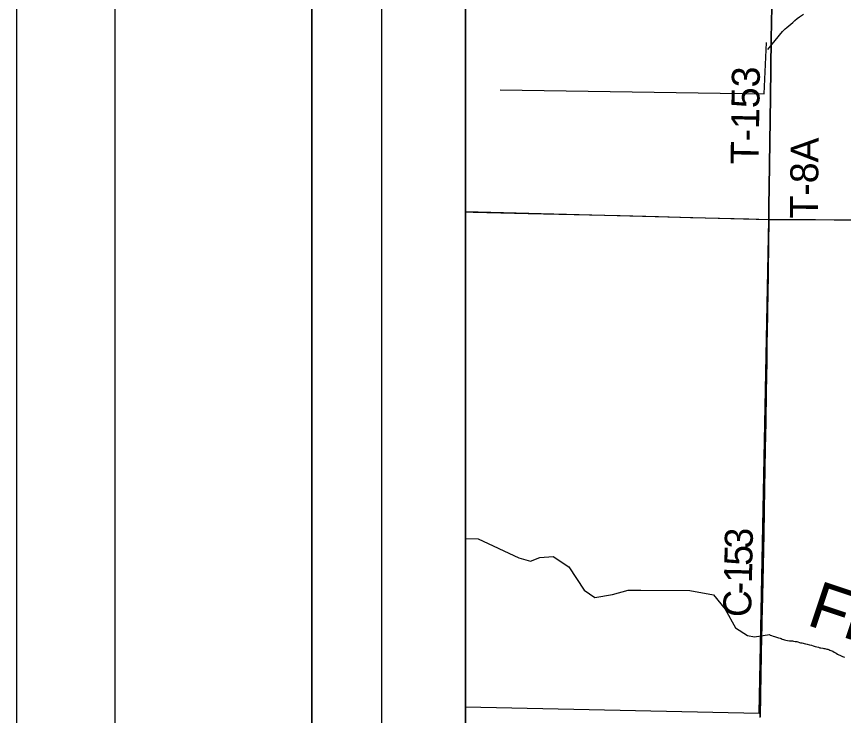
# Model space of a CAD drawing. Extents: x -483 to 680, y 0 to 440.
# Drawn here: x 0 to 84, y 177.8 to 248.8 of the extents above; entities that cross this region are included whole.
import ezdxf

# ---------------------------------------------------------------- set-up
doc = ezdxf.new("R2010")
doc.units = 0
for name, color, linetype in [('GM_X_County_Road', 7, 'Continuous'), ('GM_X_County_Road_Text', 7, 'Continuous'), ('GM_X_Minor_River', 7, 'Continuous'), ('GM_X_Minor_River_Text', 7, 'Continuous'), ('GM_X_State_Shield', 7, 'Continuous'), ('GM_X_Township_Road', 7, 'Continuous'), ('GM_X_Township_Road_Text', 7, 'Continuous'), ('SH_Border', 7, 'Continuous'), ('SH_Cut_Line', 7, 'Continuous'), ('SH_Text', 7, 'Continuous')]:
    doc.layers.add(name, color=color, linetype=linetype)

msp = doc.modelspace()

# ---------------------------------------------------------------- linework, layer by layer
at = {"layer": 'GM_X_County_Road'}
for points in [[(45.608, 228.974), (46.378, 228.954), (51.973, 228.809), (61.298, 228.597), (65.182, 228.502), (68.446, 228.413), (74.35, 228.254), (76.405, 228.209)], [(75.661, 185.894), (75.682, 186.78), (75.698, 187.554), (75.717, 188.462), (75.831, 192.963), (75.893, 196.227), (75.982, 200.889), (76.047, 204.929), (76.093, 207.57), (76.133, 210.679), (76.19, 213.71), (76.218, 215.223), (76.252, 217.206), (76.265, 218.163), (76.282, 219.286), (76.296, 220.314), (76.405, 228.209)], [(76.405, 228.209), (77.732, 228.207), (79.536, 228.205), (81.122, 228.199), (83.017, 228.168), (84.29, 228.169), (85.658, 228.165), (90.256, 228.152), (92.929, 228.14), (100.852, 228.125), (108.125, 228.103), (111.636, 228.062), (116.763, 227.999), (126.559, 227.882)], [(75.532, 177.624), (75.533, 177.672), (75.602, 182.027), (75.661, 185.894)]]:
    msp.add_lwpolyline(points, dxfattribs=at)
at = {"layer": 'GM_X_Minor_River'}
for points in [[(76.295, 245.472), (77.777, 247.291), (77.915, 247.419), (78.052, 247.548), (78.228, 247.694), (78.424, 247.859), (78.62, 248.043), (78.835, 248.207), (79.05, 248.39), (79.267, 248.611), (79.52, 248.774), (79.91, 249.065)], [(49.107, 241.377), (75.936, 240.958), (76.173, 246.166)], [(45.608, 195.807), (46.881, 195.778), (51.004, 193.866), (52.182, 193.52), (53.152, 193.898), (54.483, 193.989), (56.098, 192.92), (57.634, 190.577), (58.716, 189.833), (60.523, 190.113), (62.102, 190.583), (63.414, 190.579), (68.358, 190.546), (70.772, 190.083), (71.948, 188.635), (73.01, 186.731), (74.225, 185.948), (74.926, 185.824)], [(74.926, 185.824), (76.471, 186.059), (76.545, 185.999), (76.677, 185.976), (76.847, 185.913), (76.978, 185.852), (77.186, 185.807), (77.375, 185.743), (77.545, 185.7), (77.638, 185.659), (77.751, 185.598), (77.883, 185.574), (77.977, 185.533), (78.109, 185.491), (78.279, 185.447), (78.507, 185.421), (78.659, 185.416), (78.792, 185.411), (78.906, 185.388), (79.076, 185.364), (79.247, 185.339), (79.341, 185.317), (79.511, 185.254), (79.624, 185.231), (79.738, 185.209), (80.116, 185.12), (80.286, 185.076), (80.532, 185.03), (80.721, 184.986), (80.89, 184.923), (81.098, 184.859), (81.268, 184.816), (81.437, 184.772), (81.57, 184.729), (81.683, 184.707), (81.873, 184.681), (81.986, 184.659), (82.081, 184.636), (82.175, 184.614), (82.289, 184.591), (82.383, 184.569), (82.477, 184.528), (82.59, 184.486), (82.684, 184.445), (82.797, 184.403), (82.891, 184.362), (83.021, 184.282), (83.115, 184.222), (83.246, 184.16), (83.377, 184.08), (83.508, 184.018), (83.62, 183.958), (83.733, 183.916), (83.883, 183.835), (84.071, 183.771)]]:
    msp.add_lwpolyline(points, dxfattribs=at)
at = {"layer": 'GM_X_State_Shield'}
msp.add_lwpolyline([(45.608, 228.984), (45.608, 178.71), (75.43, 178.069), (76.384, 228.17)], close=True, dxfattribs=at)
at = {"layer": 'GM_X_Township_Road'}
for points in [[(76.405, 228.209), (76.41, 228.65), (76.418, 229.582), (76.442, 231.446), (76.566, 240.61), (76.648, 246.512), (76.701, 249.773), (76.803, 255.986), (76.879, 261.111), (76.953, 265.615), (77.008, 269.343), (77.055, 273.847), (77.077, 275.711), (77.117, 279.438), (77.163, 281.006)], [(75.661, 185.894), (75.682, 186.78), (75.698, 187.554), (75.717, 188.462), (75.831, 192.963), (75.893, 196.227), (75.982, 200.889), (76.047, 204.929), (76.093, 207.57), (76.133, 210.679), (76.19, 213.71), (76.218, 215.223), (76.252, 217.206), (76.265, 218.163), (76.282, 219.286), (76.296, 220.314), (76.405, 228.209)], [(75.532, 177.624), (75.533, 177.672), (75.602, 182.027), (75.661, 185.894)]]:
    msp.add_lwpolyline(points, dxfattribs=at)
at = {"layer": 'SH_Border'}
for points in [[(10, 430), (30, 430), (30, 10), (10, 10)], [(30, 430), (670, 430), (670, 10), (30, 10)]]:
    msp.add_lwpolyline(points, close=True, dxfattribs=at)
at = {"layer": 'SH_Cut_Line'}
msp.add_lwpolyline([(0, 0), (680, 0), (680, 440), (0, 440)], close=True, dxfattribs=at)
for points in [[(45.608, 281.486), (45.608, 55.95), (373.798, 55.95)], [(75.521, 177.7), (75.59, 182.054), (75.649, 185.922), (75.67, 186.807), (75.686, 187.581), (75.706, 188.49), (75.819, 192.991), (75.881, 196.254), (75.971, 200.917), (76.036, 204.957), (76.081, 207.598), (76.121, 210.706), (76.178, 213.737), (76.206, 215.25), (76.24, 217.233), (76.254, 218.19), (76.27, 219.313), (76.284, 220.342), (76.393, 228.237), (76.398, 228.678), (76.406, 229.61), (76.43, 231.473), (76.554, 240.637), (76.636, 246.539), (76.689, 249.801)], [(76.689, 249.801), (76.636, 246.539), (76.554, 240.637), (76.43, 231.473), (76.406, 229.61), (76.398, 228.678), (76.393, 228.237), (76.284, 220.342), (76.27, 219.313), (76.254, 218.19), (76.24, 217.233), (76.206, 215.25), (76.178, 213.737), (76.121, 210.706), (76.081, 207.598), (76.036, 204.957), (75.971, 200.917), (75.881, 196.254), (75.819, 192.991), (75.706, 188.49), (75.686, 187.581), (75.67, 186.807), (75.649, 185.922), (75.59, 182.054), (75.521, 177.7)]]:
    msp.add_lwpolyline(points, dxfattribs=at)
at = {"layer": 'SH_Text'}
for points in [[(37.108, 404.45), (394.108, 404.45), (394.108, 47.45), (37.108, 47.45)], [(45.608, 395.95), (385.608, 395.95), (385.608, 55.95), (45.608, 55.95)]]:
    msp.add_lwpolyline(points, close=True, dxfattribs=at)

# ---------------------------------------------------------------- texts
at = {"layer": 'GM_X_County_Road_Text'}
for s, rotation, p in [('3', 88.89445, (74.749, 194.764)), ('5', 88.80855, (74.713, 193.024)), ('1', 88.69429, (74.674, 191.282)), ('-', 88.6097, (74.645, 190.121)), ('C', 88.59319, (74.588, 187.805))]:
    msp.add_text(s, height=2.841, rotation=rotation, dxfattribs=at).set_placement(p)
at = {"layer": 'GM_X_Minor_River_Text'}
msp.add_text('Fivemile', height=4.7374, rotation=341.5555, dxfattribs=at).set_placement((80.112, 187.077))
at = {"layer": 'GM_X_Township_Road_Text'}
for s, rotation, p in [('T-153', 89.16012, (75.35, 233.792)), ('T-8A', 89.36558, (81.368, 228.288))]:
    msp.add_text(s, height=2.8409, rotation=rotation, dxfattribs=at).set_placement(p)

doc.saveas('drawing.dxf')
